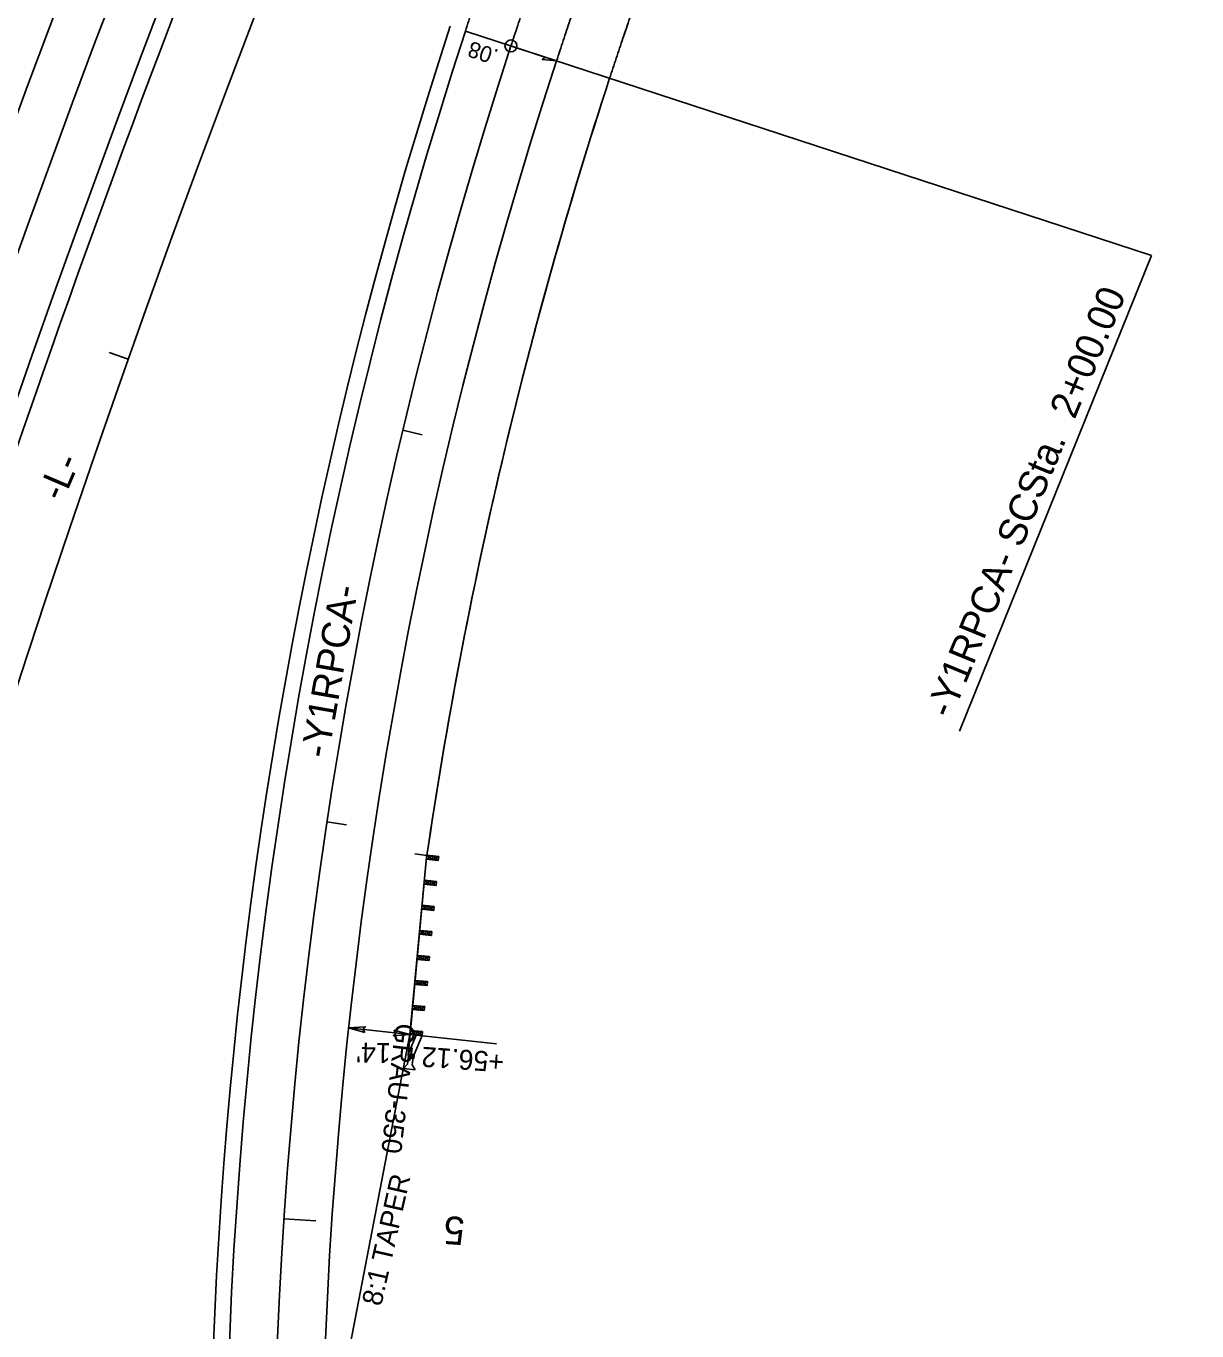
# Model space of a CAD drawing. Extents: x 2389694 to 2405615, y 547005 to 573532.
# Drawn here: x 2395404.2 to 2395697.4, y 556402.9 to 556729.7 of the extents above; entities that cross this region are included whole.
import ezdxf

# ---------------------------------------------------------------- set-up
doc = ezdxf.new("R2010")
doc.units = 0
for name, color, linetype in [('Old_Level_11', 7, 'Continuous'), ('Prop Dimension', 7, 'Continuous'), ('Prop Dimension Text', 7, 'Continuous'), ('Prop DSN Text', 7, 'Continuous'), ('Prop EOT', 7, 'Continuous'), ('Prop GRAU 350 Approach CELL', 7, 'Continuous'), ('Prop Guardrail', 7, 'Continuous'), ('Prop Horizontal Alignment', 7, 'Continuous'), ('Prop Horizontal Alignment Curve and Spiral Data', 7, 'Continuous'), ('Prop Horizontal Alignment Tick Large', 7, 'Continuous'), ('Prop Horizontal Alignment Tick Small', 7, 'Continuous'), ('Prop Lane Lines', 7, 'Continuous'), ('Prop SBG', 7, 'Continuous'), ('Prop Super Arrow 1 Lane CELL', 7, 'Continuous'), ('Prop Superelevation Label', 7, 'Continuous')]:
    doc.layers.add(name, color=color, linetype=linetype)

# ---------------------------------------------------------------- blocks, each defined once
blk = doc.blocks.new('TERM')
at = {"layer": 'Old_Level_11'}
blk.add_lwpolyline([(-0.01375, 0.00225), (0, 0), (-0.01375, -0.0025), (-0.012, 0)], close=True, dxfattribs=at)

msp = doc.modelspace()

# ---------------------------------------------------------------- linework, layer by layer
at = {"layer": 'Prop Dimension'}
msp.add_line((2395484.95, 556478.79), (2395521.95, 556474.81), dxfattribs=at)
at = {"layer": 'Prop EOT'}
for p, q in [((2395504.49, 556521.56), (2395500.32, 556477.13)), ((2395501.55, 556522.42), (2395504.55, 556521.97)), ((2395482.6, 556385.08), (2395500.32, 556477.13))]:
    msp.add_line(p, q, dxfattribs=at)
for centre, radius, start, end in [((2398729.82, 555480.32), 3559, 136.54853, 163.17888), ((2398729.82, 555480.32), 3523, 136.54853, 169.40696), ((2398729.82, 555480.32), 3573, 151.19964, 163.17888), ((2398729.82, 555480.32), 3519, 155.66284, 169.40696), ((2396666.13, 556351.64), 1216, 161.88474, 190.20655), ((2396666.13, 556351.64), 1212, 161.88474, 194.38474), ((2396666.13, 556351.64), 1188, 161.88474, 194.38474), ((2396666.13, 556351.64), 1174, 161.88474, 171.67808)]:
    msp.add_arc(centre, radius, start, end, dxfattribs=at)
for points in [[(2395589.1, 556915.27), (2395587.97, 556912.8), (2395586.85, 556910.34), (2395585.73, 556907.87), (2395584.61, 556905.4), (2395583.49, 556902.92), (2395582.37, 556900.45), (2395581.26, 556897.98), (2395580.15, 556895.5), (2395579.04, 556893.02), (2395577.93, 556890.55), (2395576.82, 556888.07), (2395575.72, 556885.58), (2395574.62, 556883.1), (2395573.52, 556880.62), (2395572.43, 556878.13), (2395571.34, 556875.65), (2395570.25, 556873.16), (2395569.16, 556870.67), (2395568.07, 556868.18), (2395566.99, 556865.69), (2395565.91, 556863.19), (2395564.84, 556860.7), (2395563.77, 556858.2), (2395562.7, 556855.7), (2395561.63, 556853.2), (2395560.56, 556850.7), (2395559.5, 556848.2), (2395558.45, 556845.7), (2395557.39, 556843.19), (2395556.34, 556840.68), (2395555.29, 556838.17), (2395554.25, 556835.66), (2395553.21, 556833.15), (2395552.17, 556830.63), (2395551.14, 556828.12), (2395550.11, 556825.6), (2395549.08, 556823.08), (2395548.06, 556820.56), (2395547.04, 556818.03), (2395546.03, 556815.51), (2395545.02, 556812.98), (2395544.01, 556810.45), (2395543.01, 556807.92), (2395542.01, 556805.39), (2395541.01, 556802.85), (2395540.02, 556800.32), (2395539.04, 556797.78), (2395538.06, 556795.24), (2395537.08, 556792.7), (2395536.1, 556790.15), (2395535.13, 556787.61), (2395534.17, 556785.06), (2395533.21, 556782.51), (2395532.26, 556779.96), (2395531.31, 556777.4), (2395530.36, 556774.85), (2395529.42, 556772.29), (2395528.48, 556769.73), (2395527.55, 556767.17), (2395526.62, 556764.6), (2395525.7, 556762.04), (2395524.79, 556759.47), (2395523.87, 556756.9), (2395522.97, 556754.33), (2395522.07, 556751.75), (2395521.17, 556749.18), (2395520.28, 556746.6), (2395519.4, 556744.02), (2395518.52, 556741.43), (2395517.64, 556738.85), (2395516.77, 556736.26), (2395515.91, 556733.67), (2395515.05, 556731.08), (2395514.21, 556728.5)], [(2395610.93, 556905.3), (2395609.81, 556902.85), (2395608.69, 556900.4), (2395607.58, 556897.95), (2395606.47, 556895.49), (2395605.36, 556893.04), (2395604.25, 556890.59), (2395603.15, 556888.13), (2395602.04, 556885.68), (2395600.94, 556883.22), (2395599.85, 556880.77), (2395598.75, 556878.31), (2395597.66, 556875.85), (2395596.57, 556873.39), (2395595.48, 556870.93), (2395594.4, 556868.47), (2395593.31, 556866), (2395592.23, 556863.54), (2395591.16, 556861.08), (2395590.08, 556858.61), (2395589.01, 556856.15), (2395587.95, 556853.68), (2395586.88, 556851.21), (2395585.82, 556848.74), (2395584.76, 556846.27), (2395583.71, 556843.8), (2395582.66, 556841.32), (2395581.61, 556838.85), (2395580.56, 556836.38), (2395579.52, 556833.9), (2395578.48, 556831.42), (2395577.45, 556828.94), (2395576.42, 556826.46), (2395575.39, 556823.98), (2395574.37, 556821.5), (2395573.35, 556819.02), (2395572.33, 556816.53), (2395571.32, 556814.04), (2395570.31, 556811.56), (2395569.31, 556809.07), (2395568.3, 556806.58), (2395567.31, 556804.08), (2395566.32, 556801.59), (2395565.33, 556799.1), (2395564.34, 556796.6), (2395563.36, 556794.1), (2395562.39, 556791.61), (2395561.42, 556789.11), (2395560.45, 556786.6), (2395559.49, 556784.1), (2395558.53, 556781.6), (2395557.57, 556779.09), (2395556.62, 556776.58), (2395555.68, 556774.07), (2395554.74, 556771.56), (2395553.81, 556769.05), (2395552.88, 556766.54), (2395551.95, 556764.02), (2395551.03, 556761.51), (2395550.11, 556758.99), (2395549.2, 556756.47), (2395548.3, 556753.95), (2395547.4, 556751.43), (2395546.5, 556748.9), (2395545.61, 556746.37), (2395544.73, 556743.85), (2395543.85, 556741.32), (2395542.97, 556738.79), (2395542.11, 556736.26), (2395541.24, 556733.72), (2395540.39, 556731.18), (2395539.53, 556728.65), (2395538.69, 556726.11), (2395537.85, 556723.57), (2395537.01, 556721.01)], [(2395623.67, 556899.49), (2395622.55, 556897.04), (2395621.44, 556894.6), (2395620.33, 556892.16), (2395619.22, 556889.72), (2395618.12, 556887.28), (2395617.02, 556884.83), (2395615.92, 556882.39), (2395614.82, 556879.95), (2395613.72, 556877.5), (2395612.63, 556875.06), (2395611.54, 556872.61), (2395610.45, 556870.17), (2395609.37, 556867.72), (2395608.29, 556865.28), (2395607.21, 556862.83), (2395606.13, 556860.38), (2395605.06, 556857.93), (2395603.99, 556855.48), (2395602.92, 556853.03), (2395601.86, 556850.58), (2395600.8, 556848.13), (2395599.74, 556845.67), (2395598.69, 556843.22), (2395597.64, 556840.77), (2395596.59, 556838.31), (2395595.54, 556835.85), (2395594.5, 556833.4), (2395593.46, 556830.94), (2395592.43, 556828.48), (2395591.4, 556826.02), (2395590.37, 556823.56), (2395589.35, 556821.1), (2395588.33, 556818.64), (2395587.31, 556816.17), (2395586.3, 556813.71), (2395585.29, 556811.24), (2395584.29, 556808.77), (2395583.29, 556806.31), (2395582.29, 556803.84), (2395581.3, 556801.37), (2395580.31, 556798.9), (2395579.33, 556796.42), (2395578.35, 556793.95), (2395577.37, 556791.48), (2395576.4, 556789), (2395575.43, 556786.52), (2395574.47, 556784.05), (2395573.51, 556781.57), (2395572.56, 556779.09), (2395571.61, 556776.61), (2395570.66, 556774.12), (2395569.72, 556771.64), (2395568.79, 556769.15), (2395567.86, 556766.67), (2395566.93, 556764.18), (2395566.01, 556761.69), (2395565.09, 556759.2), (2395564.18, 556756.71), (2395563.28, 556754.22), (2395562.37, 556751.72), (2395561.48, 556749.23), (2395560.59, 556746.73), (2395559.7, 556744.23), (2395558.82, 556741.74), (2395557.95, 556739.24), (2395557.08, 556736.73), (2395556.21, 556734.23), (2395555.35, 556731.73), (2395554.5, 556729.22), (2395553.65, 556726.71), (2395552.81, 556724.21), (2395551.97, 556721.7), (2395551.14, 556719.19), (2395550.31, 556716.64)]]:
    msp.add_spline(points, degree=3, dxfattribs=at)
at = {"layer": 'Prop GRAU 350 Approach CELL'}
for p, q in [((2395504.49, 556521.56), (2395499.84, 556471.77)), ((2395504.54, 556522.06), (2395504.43, 556521.06)), ((2395504.43, 556521.06), (2395506.03, 556521.89)), ((2395504.43, 556521.06), (2395507.41, 556520.72)), ((2395504.54, 556522.06), (2395507.53, 556521.72)), ((2395505.92, 556520.89), (2395504.54, 556522.06)), ((2395506.03, 556521.89), (2395505.92, 556520.89)), ((2395507.53, 556521.72), (2395505.92, 556520.89)), ((2395506.03, 556521.89), (2395507.41, 556520.72)), ((2395507.41, 556520.72), (2395507.53, 556521.72)), ((2395503.95, 556515.78), (2395503.86, 556514.79)), ((2395505.44, 556515.64), (2395503.86, 556514.79)), ((2395503.86, 556514.79), (2395506.84, 556514.51)), ((2395503.86, 556514.79), (2395505.35, 556514.65)), ((2395503.95, 556515.78), (2395506.94, 556515.51)), ((2395505.35, 556514.65), (2395503.95, 556515.78)), ((2395505.44, 556515.64), (2395505.35, 556514.65)), ((2395505.35, 556514.65), (2395506.94, 556515.51)), ((2395506.84, 556514.51), (2395505.44, 556515.64)), ((2395506.94, 556515.51), (2395506.84, 556514.51)), ((2395504.88, 556509.37), (2395503.27, 556508.51)), ((2395503.27, 556508.51), (2395506.31, 556508.23)), ((2395503.36, 556509.51), (2395506.4, 556509.23)), ((2395503.36, 556509.51), (2395504.79, 556508.37)), ((2395504.88, 556509.37), (2395504.79, 556508.37)), ((2395504.79, 556508.37), (2395506.4, 556509.23)), ((2395506.31, 556508.23), (2395504.88, 556509.37)), ((2395506.4, 556509.23), (2395506.31, 556508.23)), ((2395504.29, 556503.09), (2395502.68, 556502.24)), ((2395502.68, 556502.24), (2395505.72, 556501.96)), ((2395502.78, 556503.24), (2395505.81, 556502.95)), ((2395502.78, 556503.24), (2395504.2, 556502.1)), ((2395504.29, 556503.09), (2395504.2, 556502.1)), ((2395504.2, 556502.1), (2395505.81, 556502.95)), ((2395505.72, 556501.96), (2395504.29, 556503.09)), ((2395505.81, 556502.95), (2395505.72, 556501.96)), ((2395502.19, 556496.96), (2395502.1, 556495.97)), ((2395503.7, 556496.82), (2395502.1, 556495.97)), ((2395502.1, 556495.97), (2395505.12, 556495.68)), ((2395502.19, 556496.96), (2395505.21, 556496.68)), ((2395502.19, 556496.96), (2395503.61, 556495.82)), ((2395503.7, 556496.82), (2395503.61, 556495.82)), ((2395503.61, 556495.82), (2395505.21, 556496.68)), ((2395505.12, 556495.68), (2395503.7, 556496.82)), ((2395505.21, 556496.68), (2395505.12, 556495.68)), ((2395503.17, 556490.54), (2395501.51, 556489.69)), ((2395501.51, 556489.69), (2395504.64, 556489.4)), ((2395501.61, 556490.69), (2395504.73, 556490.4)), ((2395501.61, 556490.69), (2395503.07, 556489.55)), ((2395503.17, 556490.54), (2395503.07, 556489.55)), ((2395503.07, 556489.55), (2395504.73, 556490.4)), ((2395504.64, 556489.4), (2395503.17, 556490.54)), ((2395504.73, 556490.4), (2395504.64, 556489.4)), ((2395501.02, 556484.41), (2395504.01, 556484.14)), ((2395501.02, 556484.41), (2395502.42, 556483.28)), ((2395502.51, 556484.27), (2395500.93, 556483.42)), ((2395500.93, 556483.42), (2395503.91, 556483.14)), ((2395502.51, 556484.27), (2395502.42, 556483.28)), ((2395502.42, 556483.28), (2395504.01, 556484.14)), ((2395503.91, 556483.14), (2395502.51, 556484.27)), ((2395504.01, 556484.14), (2395503.91, 556483.14)), ((2395501.96, 556478), (2395500.34, 556477.14)), ((2395500.43, 556478.14), (2395503.48, 556477.86)), ((2395500.43, 556478.14), (2395501.87, 556477)), ((2395501.96, 556478), (2395501.87, 556477)), ((2395501.87, 556477), (2395503.48, 556477.86)), ((2395503.39, 556476.86), (2395501.96, 556478)), ((2395503.48, 556477.86), (2395503.39, 556476.86)), ((2395501.87, 556477), (2395499.89, 556472.26)), ((2395500.34, 556477.14), (2395503.39, 556476.86)), ((2395503.39, 556476.86), (2395501.38, 556472.13)), ((2395499.91, 556471.73), (2395499.68, 556469.69)), ((2395499.79, 556471.27), (2395501.38, 556472.13)), ((2395499.89, 556472.26), (2395501.38, 556472.13)), ((2395501.29, 556471.13), (2395499.89, 556472.26)), ((2395500.52, 556471.66), (2395499.91, 556471.73)), ((2395501.13, 556471.59), (2395500.52, 556471.66)), ((2395500.9, 556469.56), (2395501.13, 556471.59)), ((2395501.38, 556472.13), (2395501.29, 556471.13)), ((2395501.38, 556472.13), (2395501.33, 556471.63)), ((2395499.68, 556469.69), (2395498.7, 556468.62)), ((2395498.7, 556468.62), (2395501.62, 556468.29)), ((2395499.79, 556471.27), (2395501.29, 556471.13)), ((2395501.62, 556468.29), (2395500.9, 556469.56))]:
    msp.add_line(p, q, dxfattribs=at)
at = {"layer": 'Prop Guardrail'}
for centre, radius, start, end in [((2398729.82, 555480.32), 3573, 151.45837, 163.17888), ((2396666.13, 556351.64), 1174, 161.88474, 171.67808)]:
    msp.add_arc(centre, radius, start, end, dxfattribs=at)
msp.add_spline([(2395550.31, 556716.64), (2395551.14, 556719.19), (2395551.97, 556721.7), (2395552.81, 556724.21), (2395553.65, 556726.71), (2395554.5, 556729.22), (2395555.35, 556731.73), (2395556.21, 556734.23), (2395557.08, 556736.73), (2395557.95, 556739.24), (2395558.82, 556741.74), (2395559.7, 556744.23), (2395560.59, 556746.73), (2395561.48, 556749.23), (2395562.37, 556751.72), (2395563.28, 556754.22), (2395564.18, 556756.71), (2395565.09, 556759.2), (2395566.01, 556761.69), (2395566.93, 556764.18), (2395567.86, 556766.67), (2395568.79, 556769.15), (2395569.72, 556771.64), (2395570.66, 556774.12), (2395571.61, 556776.61), (2395572.56, 556779.09), (2395573.51, 556781.57), (2395574.47, 556784.05), (2395575.43, 556786.52), (2395576.4, 556789), (2395577.37, 556791.48), (2395578.35, 556793.95), (2395579.33, 556796.42), (2395580.31, 556798.9), (2395581.3, 556801.37), (2395582.29, 556803.84), (2395583.29, 556806.31), (2395584.29, 556808.77), (2395585.29, 556811.24), (2395586.3, 556813.71), (2395587.31, 556816.17), (2395588.33, 556818.64), (2395589.35, 556821.1), (2395590.37, 556823.56), (2395591.4, 556826.02), (2395592.43, 556828.48), (2395593.46, 556830.94), (2395594.5, 556833.4), (2395595.54, 556835.85), (2395596.59, 556838.31), (2395597.64, 556840.77), (2395598.69, 556843.22), (2395599.74, 556845.67), (2395600.8, 556848.13), (2395601.86, 556850.58), (2395602.92, 556853.03), (2395603.99, 556855.48), (2395605.06, 556857.93), (2395606.13, 556860.38), (2395607.21, 556862.83), (2395608.29, 556865.28), (2395609.37, 556867.72), (2395610.45, 556870.17), (2395611.54, 556872.61), (2395612.63, 556875.06), (2395613.72, 556877.5), (2395614.82, 556879.95), (2395615.92, 556882.39), (2395617.02, 556884.83), (2395618.12, 556887.28), (2395619.22, 556889.72), (2395620.33, 556892.16), (2395621.44, 556894.6), (2395622.55, 556897.04), (2395623.67, 556899.49)], degree=3, dxfattribs=at)
at = {"layer": 'Prop Horizontal Alignment'}
for centre, radius, start, end in [((2398729.82, 555480.32), 3500, 136.54853, 177.15578), ((2396666.13, 556351.64), 1200, 161.88474, 194.38474)]:
    msp.add_arc(centre, radius, start, end, dxfattribs=at)
msp.add_spline([(2395600.01, 556910.29), (2395598.89, 556907.83), (2395597.77, 556905.37), (2395596.65, 556902.91), (2395595.54, 556900.45), (2395594.42, 556897.98), (2395593.31, 556895.52), (2395592.2, 556893.05), (2395591.1, 556890.59), (2395589.99, 556888.12), (2395588.89, 556885.66), (2395587.79, 556883.19), (2395586.69, 556880.72), (2395585.59, 556878.25), (2395584.5, 556875.77), (2395583.41, 556873.3), (2395582.32, 556870.83), (2395581.24, 556868.35), (2395580.16, 556865.87), (2395579.08, 556863.4), (2395578, 556860.92), (2395576.93, 556858.44), (2395575.86, 556855.95), (2395574.79, 556853.47), (2395573.73, 556850.99), (2395572.67, 556848.5), (2395571.61, 556846.01), (2395570.56, 556843.53), (2395569.5, 556841.04), (2395568.46, 556838.54), (2395567.41, 556836.05), (2395566.37, 556833.56), (2395565.33, 556831.06), (2395564.3, 556828.56), (2395563.27, 556826.07), (2395562.24, 556823.57), (2395561.22, 556821.06), (2395560.2, 556818.56), (2395559.19, 556816.06), (2395558.17, 556813.55), (2395557.17, 556811.04), (2395556.16, 556808.53), (2395555.16, 556806.02), (2395554.17, 556803.51), (2395553.18, 556800.99), (2395552.19, 556798.48), (2395551.21, 556795.96), (2395550.23, 556793.44), (2395549.25, 556790.92), (2395548.28, 556788.4), (2395547.32, 556785.87), (2395546.35, 556783.35), (2395545.4, 556780.82), (2395544.45, 556778.29), (2395543.5, 556775.76), (2395542.56, 556773.23), (2395541.62, 556770.69), (2395540.68, 556768.16), (2395539.76, 556765.62), (2395538.83, 556763.08), (2395537.91, 556760.54), (2395537, 556757.99), (2395536.09, 556755.45), (2395535.19, 556752.9), (2395534.29, 556750.35), (2395533.4, 556747.8), (2395532.51, 556745.25), (2395531.63, 556742.69), (2395530.75, 556740.14), (2395529.88, 556737.58), (2395529.01, 556735.02), (2395528.15, 556732.45), (2395527.3, 556729.89), (2395526.45, 556727.32), (2395525.61, 556724.76)], degree=3, dxfattribs=at)
at = {"layer": 'Prop Horizontal Alignment Curve and Spiral Data'}
for p, q in [((2395527.03, 556724.29), (2395686.05, 556672.27)), ((2395686.05, 556672.27), (2395637.92, 556553.14))]:
    msp.add_line(p, q, dxfattribs=at)
msp.add_circle((2395525.61, 556724.76), 1.5, dxfattribs=at)
at = {"layer": 'Prop Horizontal Alignment Tick Large'}
msp.add_line((2395468.75, 556430.99), (2395476.74, 556430.46), dxfattribs=at)
at = {"layer": 'Prop Horizontal Alignment Tick Small'}
for p, q in [((2395525.61, 556724.76), (2395530.36, 556723.2)), ((2395429.74, 556646.27), (2395425.02, 556647.94)), ((2395498.51, 556628.53), (2395503.37, 556627.38)), ((2395479.51, 556530.38), (2395484.46, 556529.63))]:
    msp.add_line(p, q, dxfattribs=at)
at = {"layer": 'Prop Lane Lines'}
for radius in [3547, 3535]:
    msp.add_arc((2398729.82, 555480.32), radius, 136.54853, 169.40696, dxfattribs=at)
at = {"layer": 'Prop SBG'}
msp.add_arc((2396666.13, 556351.64), 1174, 161.88474, 171.65776, dxfattribs=at)
msp.add_spline([(2395623.67, 556899.5), (2395622.55, 556897.05), (2395621.44, 556894.61), (2395620.33, 556892.17), (2395619.23, 556889.72), (2395618.12, 556887.28), (2395617.02, 556884.84), (2395615.92, 556882.4), (2395614.82, 556879.95), (2395613.73, 556877.51), (2395612.63, 556875.07), (2395611.54, 556872.62), (2395610.46, 556870.18), (2395609.37, 556867.73), (2395608.29, 556865.28), (2395607.21, 556862.83), (2395606.14, 556860.39), (2395605.07, 556857.94), (2395604, 556855.49), (2395602.93, 556853.04), (2395601.86, 556850.59), (2395600.8, 556848.13), (2395599.75, 556845.68), (2395598.69, 556843.23), (2395597.64, 556840.77), (2395596.59, 556838.32), (2395595.55, 556835.86), (2395594.51, 556833.4), (2395593.47, 556830.94), (2395592.43, 556828.49), (2395591.4, 556826.03), (2395590.38, 556823.56), (2395589.35, 556821.1), (2395588.33, 556818.64), (2395587.32, 556816.18), (2395586.31, 556813.71), (2395585.3, 556811.25), (2395584.29, 556808.78), (2395583.29, 556806.31), (2395582.3, 556803.84), (2395581.3, 556801.37), (2395580.31, 556798.9), (2395579.33, 556796.43), (2395578.35, 556793.96), (2395577.37, 556791.48), (2395576.4, 556789.01), (2395575.44, 556786.53), (2395574.47, 556784.05), (2395573.51, 556781.57), (2395572.56, 556779.09), (2395571.61, 556776.61), (2395570.67, 556774.13), (2395569.73, 556771.65), (2395568.79, 556769.16), (2395567.86, 556766.67), (2395566.93, 556764.19), (2395566.01, 556761.7), (2395565.1, 556759.21), (2395564.19, 556756.72), (2395563.28, 556754.22), (2395562.38, 556751.73), (2395561.48, 556749.24), (2395560.59, 556746.74), (2395559.71, 556744.24), (2395558.83, 556741.74), (2395557.95, 556739.24), (2395557.08, 556736.74), (2395556.22, 556734.24), (2395555.36, 556731.73), (2395554.51, 556729.23), (2395553.66, 556726.72), (2395552.82, 556724.21), (2395551.98, 556721.7), (2395551.15, 556719.19), (2395550.31, 556716.65)], degree=3, dxfattribs=at)
at = {"layer": 'Prop Super Arrow 1 Lane CELL'}
msp.add_line((2395514.2, 556728.49), (2395537.01, 556721.03), dxfattribs=at)
msp.add_lwpolyline([(2395537.01, 556721.03), (2395533.44, 556721.35), (2395534.21, 556721.94)], close=True, dxfattribs=at)

# ---------------------------------------------------------------- block references
at = {"layer": 'Prop Dimension', "xscale": 300.00000000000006, "yscale": 300.00000000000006}
for p, rotation in [((2395484.95, 556478.79), 173.8560554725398), ((2395500.32, 556477.13), -6.143944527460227)]:
    msp.add_blockref('TERM', p, dxfattribs=dict(at, rotation=rotation))

# ---------------------------------------------------------------- texts
at = {"layer": 'Prop Dimension'}
for s, rotation, p in [('-L-', 66.8522, (2395413.36, 556610.36)), ('-Y1RPCA-', 79.9854, (2395479.79, 556546.1))]:
    msp.add_text(s, height=7, rotation=rotation, dxfattribs=at).set_placement(p)
at = {"layer": 'Prop Dimension Text'}
for s, rotation, p in [("14'", 178.8476, (2395495.57, 556474.98)), ('+56.12', 175.8793, (2395524.01, 556472.61)), ('8:1 TAPER', 77.2487, (2395493.09, 556408.91))]:
    msp.add_text(s, height=5, rotation=rotation, dxfattribs=at).set_placement(p)
at = {"layer": 'Prop DSN Text'}
msp.add_text('GRAU-350', height=5, rotation=263.6748, dxfattribs=at).set_placement((2395496.73, 556480.13))
at = {"layer": 'Prop Horizontal Alignment Curve and Spiral Data'}
for s, rotation, p in [('-Y1RPCA- SCSta.  2+00.00', 67.5928, (2395635.83, 556556.02)), ('5', 176.2087, (2395514.21, 556431.35))]:
    msp.add_text(s, height=7, rotation=rotation, dxfattribs=at).set_placement(p)
at = {"layer": 'Prop Superelevation Label'}
msp.add_text('.08', height=4, rotation=161.8847, dxfattribs=at).set_placement((2395522.73, 556723.73))

doc.saveas('drawing.dxf')
